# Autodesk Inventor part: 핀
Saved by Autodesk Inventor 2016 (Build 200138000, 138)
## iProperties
Created: 2024-08
Part Number: 핀
Material: 일반
Document SubType Name: Modeling
Designer: pc-2
Density: 1 g/cm^3
Appearance: 기본값
Author: jhkim
Sending System: Autodesk Inventor 2025
Preprocessor: ST-DEVELOPER v20
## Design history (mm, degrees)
node "핀1"
node "솔리드2"
node "솔리드1"
